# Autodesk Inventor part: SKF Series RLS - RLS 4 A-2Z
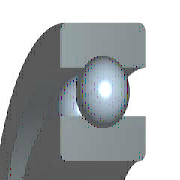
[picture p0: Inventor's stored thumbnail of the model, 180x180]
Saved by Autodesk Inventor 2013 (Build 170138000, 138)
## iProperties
IsCustomPart: 0
Created: 2008-02
Part Number: SKF Series RLS - RLS 4 A-2Z
Material: Steel, Mild
Description: Deep Groove Ball Bearings with Two Shields
Document SubType Name: Modeling
Standard: SKF Series RLS
Designer: tangg
Language: en-US
Size Designation: RLS 4 A-2Z
Categories: <MemberInstance><Categories><Category DisplayName="Shaft Parts" InternalName="7f7aeb1f-a693-4053-b835-cee3144e0d98" Mnemonic="SHFT"><Category DisplayName="Beari
Density: 7.86 g/cm^3
Mass: 36.4326 g
Surface Area: 44.4354 cm^2
Volume: 4.63519 cm^3
Author: tangg
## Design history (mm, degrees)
node "Sketch1"
node "WorkPoint1"
node "WorkAxis1"
node "WorkPlane3"
node "WorkPlane4"
node "Sketch4"
node "WorkPoint2"
pattern_circular "PolarArray1" dims "d17" = 59.76923 (= msp_pocet), angle "d19" = 360 deg
fillet "Fillet1" dims "d20" = 0.79375 (= r)
body "Solid1"
revolve "Revolution1" stored, may be unused: angle "d6" = 360 deg
revolve "Revolution2" stored, may be unused: angle "d10" = 360 deg
revolve "Revolution3" stored, may be unused: angle "d16" = 360 deg
sketch "Sketch2"
  geometry: L1 (6.35, 9.525)-(16.669, 9.525); L2 (6.35, 0)-(6.35, 9.525); L3 (16.669, 0)-(6.35, 0); L4 (16.669, 9.525)-(16.669, 0); L5 (0, 0)-(0, 20); L6 (0, 0)-(0, 20); L7 (-3.334, 0)-(20.003, 0) reference
  constraints: 12 end point, 3 vertical, 2 horizontal, 1 collinear, 1 other
  dimensions: "d1" = 12.7 diameter of L1.start L5 (= Diam); "d3" = 33.3375 diameter of L1.end L5 (= DD); "d5" = 9.525 distance of L2.start L1.start (= msp_mdtd2)
sketch "Sketch3"
  geometry: L1 (13.367, 9.525)-(13.367, 7.239); L2 (9.652, 9.525)-(13.367, 9.525); L3 (9.652, 7.239)-(9.652, 9.525); L4 (9.652, 0)-(9.652, 2.286); L5 (13.367, 0)-(9.652, 0); L6 (13.367, 2.286)-(13.367, 0); L7 (16.669, 0)-(-16.669, 0) reference; L8 (16.669, 9.525)-(-16.669, 9.525) reference; L9 (0, -42.29)-(0, 61.29); L10 (0, 82.007)-(0, -63.007) reference; A1 r 3.096 centre (11.509, 4.763) between (13.367, 2.286) and (13.367, 7.239); A2 r 3.096 centre (11.509, 4.763) between (9.652, 7.239) and (9.652, 2.286)
  constraints: 14 end point, 4 collinear, 4 point on circle, 4 vertical, 2 centre point, 2 concentric, 2 horizontal, 2 point on line
  dimensions: "d9" = 6.19125 diameter of A1 (= msp_mdtd6); "d21" = 9.652 distance between parallel lines of L9 L4 (= 0.5 x msp_d1); "d22" = 11.50937 distance from line of L9 A1.centre (= 0.5 x msp_ds); "d23" = 13.36675 distance between parallel lines of L9 L6 (= 0.5 x msp_dd1)
sketch "Sketch5"
  geometry: L1 (11.509, 1.667)-(11.509, 7.858); L2 (13.367, 0)-(-13.367, 0) reference; L3 (11.509, 1.667)-(11.509, 7.858); A1 r 3.096 centre (11.509, 4.763) between (11.509, 1.667) and (11.509, 7.858); A2 r 3.096 centre (11.509, 4.763) between (13.367, 2.286) and (13.367, 7.239) reference
  constraints: 4 end point, 2 point on circle, 1 centre point, 1 concentric, 1 vertical
  dimensions: "d13" = 0 horizontal distance of A1.centre L1.start; "d15" = 6.19135 diameter of A1 (computed from msp_mdtd6)
other parameters: "Diam" = 12.7 [user parameter; used in 3 equation terms], "DD" = 33.3375 [user parameter; used in 3 equation terms], "B" = 9.525 [user parameter; used in 1 equation term], "r" = 0.79375 [user parameter; used in 1 equation term], "msp_ds" = 23.01875 (= 0.5 x Diam + 0.5 x DD) [user parameter; used in 5 equation terms], "msp_d0" = 6.19125 (= -0.3 x Diam + 0.3 x DD) [user parameter; used in 4 equation terms], "msp_d1" = 19.304 (= msp_ds - 0.6 x msp_d0) [user parameter; used in 1 equation term], "msp_dd1" = 26.7335 (= msp_ds + 0.6 x msp_d0) [user parameter; used in 1 equation term], "msp_pom" = 34.52813 (= 1.5 x msp_ds) [user parameter; used in 1 equation term], "msp_mdtd2" = 9.525 (= B) [user parameter; used in 3 equation terms], "msp_mdtd4" = 23.01875 (= msp_ds) [user parameter], "msp_mdtd6" = 6.19125 (= msp_d0) [user parameter; used in 2 equation terms], "msp_mdtd7" = 4.7625 (= 0.5 x msp_mdtd2) [user parameter], "msp_pocet" = 59.76923 (computed from msp_d0, msp_pom) [user parameter; used in 1 equation term], "d2" = 72 (derived), "d4" = 19 (derived), "d7" = 0, "d8" = 15.6 (derived), "d11" = -9.525 (computed from msp_mdtd2), "d12" = 0 (derived), "d14" = 15.6001 (derived), "d26" = 0, "d31" = 0, "d32" = 0, "d33" = 0, "d34" = 0
